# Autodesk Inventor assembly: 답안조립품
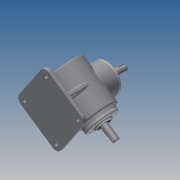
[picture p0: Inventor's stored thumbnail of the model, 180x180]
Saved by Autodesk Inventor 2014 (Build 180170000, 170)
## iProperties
Created: 2015-07
Part Number: 답안조립품
Document SubType Name: Assembly
Designer: SDA21
Author: SDA21
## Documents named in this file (13)
- C:\Users\SDA21\Desktop\450705V1022\답안조립품.iam
- C:\Users\SDA21\Desktop\450705V1022\본체.ipt
- C:\Users\SDA21\Desktop\450705V1022\450705V1022\메인 축.ipt
- 메인 축.ipt
- C:\Users\SDA21\Desktop\450705V1022\450705V1022\키 5x5.ipt
- C:\Users\SDA21\Desktop\450705V1022\450705V1022\서브 베벨기어.ipt
- C:\Users\SDA21\Desktop\450705V1022\450705V1022\메인 베벨기어.ipt
- C:\Users\SDA21\Desktop\450705V1022\450705V1022\커버.ipt
- C:\Users\SDA21\Desktop\450705V1022\450705V1022\베어링 6203.ipt
- C:\Users\SDA21\Desktop\450705V1022\450705V1022\서브 축.ipt
- 서브 축.ipt
- C:\Users\SDA21\Desktop\450705V1022\450705V1022\키 4x4.ipt
- C:\Users\SDA21\Desktop\450705V1022\450705V1022\오일실.ipt
